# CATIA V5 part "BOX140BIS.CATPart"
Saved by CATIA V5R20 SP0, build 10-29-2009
Part number: BOX140BIS
Bounding box of the stored display mesh (mm): x 0 to 216, y -20 to 55, z -41.5 to 15
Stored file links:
  C:\Users\Utente\Desktop\IO LAVORO\3D X SITO CF\X SITO\PLASTICA\BOX\BOX140BIS.CATPart
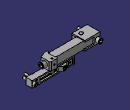
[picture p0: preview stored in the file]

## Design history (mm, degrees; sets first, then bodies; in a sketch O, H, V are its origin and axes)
Set1
  DatumSurface1 to DatumSurface16 "_ZH90/1 BIS_head"
  DatumSurface17 to DatumSurface34 "_ZH90/1 BIS_screw1"
  DatumSurface35 to DatumSurface55 "_ZH90/1 BIS_hand"
  DatumSurface56 to DatumSurface73 "_ZH90/1 BIS_screw2"
  DatumSurface74 to DatumSurface94 "_ZH90/1 BIS_he"
  DatumSurface95 to DatumSurface109 "_ZH90/1 BIS_screw3"
  DatumSurface110 to DatumSurface117 "_ZH90/1 BIS_stift1"
  DatumSurface118 to DatumSurface127 "_ZH90/1 BIS_stift2"
  DatumSurface128 to DatumSurface589 "_ZH90/01_body"
  DatumSurface590 to DatumSurface607 "_M8-5"
  DatumSurface608 to DatumSurface627 "_ST2"
  DatumSurface628 to DatumSurface673 "_ZH90/01_foot1u"
  DatumSurface674 to DatumSurface696 "_ZH90/01_foot1d"
  DatumSurface697 to DatumSurface714 "_M5-1"
  DatumSurface715 to DatumSurface737 "_ZH90/01_foot2u"
  DatumSurface738 to DatumSurface771 "_ZH90/01_foot2d"
  DatumSurface772 to DatumSurface789 "_M5-2"
Body1 (main body)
